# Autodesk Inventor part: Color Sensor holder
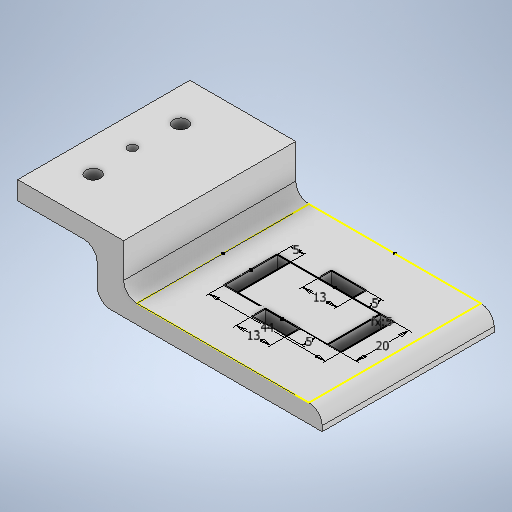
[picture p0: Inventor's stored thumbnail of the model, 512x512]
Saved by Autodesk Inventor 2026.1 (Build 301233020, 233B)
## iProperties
Created: 2026-11
Part Number: Color Sensor holder
Material: Generic
Document SubType Name: Modeling
Designer: hp
Density: 1 g/cm^3
Appearance: Default
Author: hp
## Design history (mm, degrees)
sketch "Sketch1"
  geometry: L1 (0, 0)-(0, 25); L2 (0, 25)-(10, 25); L3 (10, 25)-(10, 7); L4 (10, 7)-(85, 7); L5 (85, 7)-(85, 0); L6 (85, 0)-(0, 0); L7 (47.5, 7)-(47.5, 0); L8 (10, 0)-(95, 0); L9 (0, 18)-(-30, 18); L10 (-30, 18)-(-30, 25); L11 (-30, 25)-(0, 25); 1 further point
  constraints: 22 end point, 8 perpendicular, 2 point on line, 2 symmetric about line, 1 horizontal, 1 midpoint, 1 vertical
  dimensions: "d0" = 25 distance of L1.start L1.end; "d1" = 10 distance of L1.end L2.end; "d2" = 18 distance of L2.end L3.end; "d3" = 75 distance of L3.end L4.end; "d18" = 30 distance of L9.start L9.end; "d19" = 7 distance of L9.end L10.end
extrude "Extrusion1" new body sketch "Sketch1" distance "d4" = 65; taper "d5" = 0 deg
fillet "Fillet1" dims "d6" = 5
fillet "Fillet2" dims "d7" = 5
sketch "Sketch2"
  geometry: L1 (65, 65)-(65, 0) reference; L2 (65, 65)-(0, 65) reference; L3 (0, 0)-(0, 65) reference; L4 (65, 0)-(0, 0) reference; L5 (10.5, 42.5)-(54.5, 42.5); L6 (54.5, 42.5)-(54.5, 22.5); L7 (54.5, 22.5)-(10.5, 22.5); L8 (10.5, 22.5)-(10.5, 42.5); L9 (26, 22.5)-(39, 22.5); L10 (39, 22.5)-(39, 17.5); L11 (39, 17.5)-(26, 17.5); L12 (26, 17.5)-(26, 22.5); L13 (26, 47.5)-(39, 47.5); L14 (39, 47.5)-(39, 42.5); L15 (26, 42.5)-(26, 47.5); L16 (39, 42.5)-(26, 42.5); L17 (15.5, 22.5)-(15.5, 42.5); L18 (49.5, 22.5)-(49.5, 42.5); 10 further points
  constraints: 28 end point, 7 midpoint, 6 parallel, 5 perpendicular, 4 point on line, 3 horizontal, 1 horizontal alignment, 1 vertical alignment
  dimensions: "d8" = 44 distance of L6.end L7.end; "d9" = 20 distance of L5.end L6.end; "d10" = 13 distance of L10.end L11.end; "d11" = 5 distance of L9.end L10.end; "d12" = 13 distance of L14.end L15.start; "d13" = 5 distance of L13.end L14.end; "d16" = 5 distance between parallel lines of L17 L8; "d17" = 5 distance between parallel lines of L6 L18 (= d16)
extrude "Extrusion2" cut sketch "Sketch2" extent not by distance; stored distance "d14" = 60; taper "d15" = 0 deg
fillet "Fillet3" dims "d20" = 5
sketch "Sketch3"
  geometry: 1 further point
hole "Hole1" sketch "Sketch3" at (11.3, 32.987) diameter "d21" = 3.4; stored, may be unused: countersink angle "d25" = 90 deg, drill point angle "d27" = 0 deg; dims "d22" = 6, "d23" = 4, "d24" = 2, "d26" = 8
sketch "Sketch4"
  geometry: L1 (25, 65)-(25, 0) reference; L2 (0, 65)-(25, 65) reference; L3 (0, 0)-(0, 65) reference; L4 (0, 0)-(25, 0) reference; C1 r 1.7 at (11.3, 32.987) reference; C2 r 2.5 at (12.5, 49); C3 r 2.5 at (12.5, 16); 5 further points
  constraints: 2 centre point, 2 coincident, 2 midpoint, 2 vertical alignment
  dimensions: "d28" = 5 diameter of C2; "d29" = 5 diameter of C3 (= d28); "d30" = 16 distance from line of L2 C2.centre; "d31" = 16 distance from line of L4 C3.centre (= d30)
  node "Projected Loop2"
sketch "Sketch5"
  geometry: 2 further points
hole "Hole2" sketch "Sketch5" at (12.5, 49), (12.5, 16) diameter "d32" = 5.5; stored, may be unused: countersink angle "d36" = 90 deg, drill point angle "d38" = 0 deg; dims "d33" = 6, "d34" = 4, "d35" = 2, "d37" = 8
body "Solid1"
node "Projected Loop1"
